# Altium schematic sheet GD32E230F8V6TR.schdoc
size 127 x 101 mm
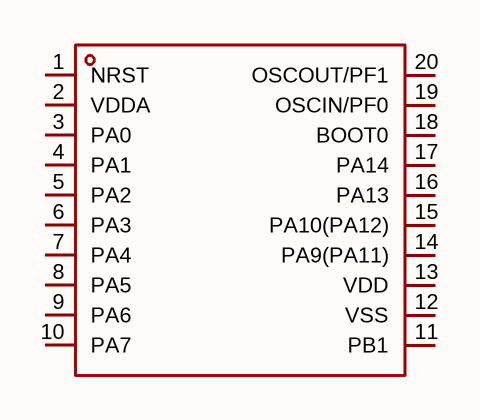
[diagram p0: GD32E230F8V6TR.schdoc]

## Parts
U?  gd32e230f8v6tr  [LGA-20_L3.0-W3.0-P0.50-BL]  (value not drawn)

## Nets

Not connected (* = marked no-connect by the designer): U? 1(NRST) 2(VDDA) 3(PA0) 4(PA1) 5(PA2) 6(PA3) 7(PA4) 8(PA5) 9(PA6) 10(PA7) 11(PB1) 12(VSS) 13(VDD) 14(PA9(PA11)) 15(PA10(PA12)) 16(PA13) 17(PA14) 18(BOOT0) 19(OSCIN/PF0) 20(OSCOUT/PF1)

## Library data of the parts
U? = gd32e230f8v6tr: CPU内核:ARM Cortex-M系列;CPU最大主频:72MHz;; Manufacturer: GigaDevice(兆易创新); AddInBom: yes; ModelId: b2a2bba84ecf4d988ee352856dce047f; ModelTransform: 118.11,118.11,0,90,0,0,0,0,0; CPU Maximum Speed: 72MHz; Program Storage Size: 64KB; Program Memory Type: FLASH; Number of I/O: 15; ADC (Bit): 12bit; Voltage - Supply: 1.8V~3.6V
